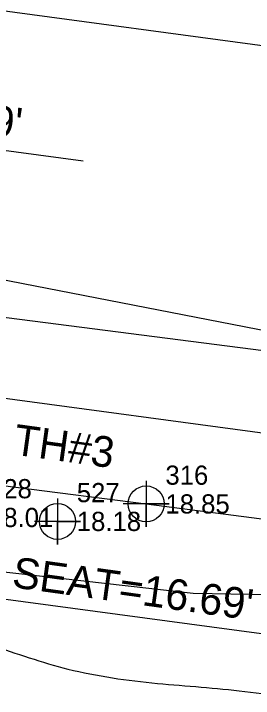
# Model space of a CAD drawing. Extents: x 2627243 to 2636458, y 566398 to 571062.
# Drawn here: x 2634722 to 2634753.1, y 569047.1 to 569136.3 of the extents above; entities that cross this region are included whole.
import ezdxf

# ---------------------------------------------------------------- set-up
doc = ezdxf.new("R2010")
doc.units = 0
for name, color, linetype in [('COGO Default Chain', 7, 'Continuous'), ('Exist Horizontal Alignment', 7, 'Continuous'), ('Exist Horizontal Baseline Alignment', 7, 'Continuous'), ('Exist Right of Way Line', 7, 'Continuous'), ('Exist Roads EOP', 7, 'Continuous'), ('Exist Roads EOP Cogo Elevation', 7, 'Continuous'), ('Exist Roads EOP Cogo Number', 7, 'Continuous'), ('Exist Roads EOP Cogo Point CELL', 7, 'Continuous'), ('Exist Structure Major Bridge Seat Top Elevation', 7, 'Continuous'), ('Exist Utilities Water Test Hole SUE Text', 7, 'Continuous'), ('Exist Utilities Water UG Line', 7, 'Continuous'), ('Exist Utilities Water UG Line Cogo Elevation', 7, 'Continuous'), ('Exist Utilities Water UG Line Cogo Number', 7, 'Continuous'), ('Exist Utilities Water UG Line Cogo Point CELL', 7, 'Continuous'), ('Exist Utilities Water UG Line SUE', 7, 'Continuous'), ('Exist Vegetation Woods Line', 7, 'Continuous')]:
    doc.layers.add(name, color=color, linetype=linetype)

# ---------------------------------------------------------------- blocks, each defined once
blk = doc.blocks.new('EXIST ROADS EOP COGO POINT')
at = {"layer": 'Exist Roads EOP Cogo Point CELL'}
blk.add_lwpolyline([(0, 0.06), (0, -0.06), (0, 0), (0.06, 0), (-0.06, 0)], dxfattribs=at)
blk.add_circle((0, 0), 0.0469, dxfattribs=at)
blk = doc.blocks.new('EXIST UTILITIES WATER UG LINE COGO POINT')
at = {"layer": 'Exist Utilities Water UG Line Cogo Point CELL'}
blk.add_lwpolyline([(0, 0.06), (0, -0.06), (0, 0), (0.06, 0), (-0.06, 0)], dxfattribs=at)
blk.add_circle((0, 0), 0.0469, dxfattribs=at)

msp = doc.modelspace()

# ---------------------------------------------------------------- linework, layer by layer
at = {"layer": 'COGO Default Chain'}
msp.add_line((2634072.78, 569173.542), (2634872.745, 569065.698), dxfattribs=at)
msp.add_line((2634072.78, 569173.542), (2634872.745, 569065.698), dxfattribs=at)
at = {"layer": 'Exist Horizontal Alignment'}
msp.add_line((2634072.78, 569173.542), (2634872.745, 569065.698), dxfattribs=at)
at = {"layer": 'Exist Horizontal Baseline Alignment'}
msp.add_line((2634680.61, 569109.426), (2635129.789, 569021.834), dxfattribs=at)
at = {"layer": 'Exist Right of Way Line'}
msp.add_line((2632427.744, 569445.763), (2634879.425, 569115.25), dxfattribs=at)
at = {"layer": 'Exist Roads EOP'}
msp.add_lwpolyline([(2634756.154, 569092.132), (2634708.467, 569098.258), (2634691.47, 569100.768), (2634667.356, 569105.661), (2634677.917, 569078.08), (2634688.445, 569077.775), (2634705.225, 569076.779), (2634739.193, 569072.427), (2634781.279, 569066.947)], dxfattribs=at)
at = {"layer": 'Exist Structure Major Bridge Seat Top Elevation'}
for points in [[(2634664.402, 569107.828), (2634688.681, 569122.796), (2634731.011, 569117.111)], [(2634677.043, 569076.496), (2634717.336, 569060.479), (2634757.082, 569055.141)]]:
    msp.add_lwpolyline(points, dxfattribs=at)
at = {"layer": 'Exist Utilities Water UG Line'}
msp.add_lwpolyline([(2634491.938, 569094.669), (2634504.797, 569090.483), (2634523.376, 569085.838), (2634745.287, 569060.808)], dxfattribs=at)
at = {"layer": 'Exist Utilities Water UG Line SUE'}
msp.add_lwpolyline([(2634745.287, 569060.808), (2634772.297, 569060.34), (2634799.288, 569058.161), (2634834.917, 569055.152), (2634876.42, 569050.415), (2634893.166, 569047.225), (2634922.728, 569041.343), (2634951.296, 569036.029), (2634995.745, 569027.256), (2635043.17, 569015.782), (2635070.418, 569008.301), (2635098.215, 568999.229), (2635119.896, 568992.516), (2635152.298, 568983.109), (2635187.641, 568971.231), (2635214.866, 568960.801)], dxfattribs=at)
at = {"layer": 'Exist Vegetation Woods Line'}
msp.add_spline([(2634648.605, 568711.487), (2634653.173, 568721.16), (2634653.751, 568723.17), (2634653.062, 568734.655), (2634652.681, 568736.88), (2634653.811, 568745.816), (2634654.682, 568748.012), (2634657.462, 568751.415), (2634662.006, 568762.101), (2634666.134, 568771.495), (2634670.477, 568781.848), (2634675.662, 568793.145), (2634680.221, 568804.456), (2634684.286, 568815.25), (2634687.607, 568827.217), (2634691.496, 568836.665), (2634694.841, 568847.62), (2634698.696, 568859.72), (2634702.614, 568870.42), (2634706.547, 568881.746), (2634708.602, 568893.118), (2634707.859, 568904.363), (2634707.859, 568914.434), (2634708.964, 568924.382), (2634711.312, 568935.939), (2634713.66, 568947.496), (2634714.717, 568959.47), (2634715.613, 568970.724), (2634714.708, 568981.25), (2634713.309, 568991.258), (2634709.845, 569001.605), (2634703.677, 569011.679), (2634697.548, 569021.366), (2634694.645, 569026.929), (2634691.128, 569037.035), (2634687.161, 569048.502), (2634684.142, 569055.224), (2634683.989, 569062.938), (2634686.083, 569063.851), (2634688.255, 569063.992), (2634698.877, 569060.848), (2634708.912, 569057.331), (2634719.002, 569054.055), (2634728.998, 569050.925), (2634740.663, 569049.057), (2634752.01, 569048.015), (2634763.876, 569046.479), (2634774.812, 569046.411), (2634786.684, 569047.139), (2634798.51, 569045.99), (2634811.388, 569044.478), (2634822.056, 569043.211), (2634833.271, 569042.703), (2634842.818, 569040.933), (2634849.22, 569038.612), (2634860.807, 569037.516), (2634873.074, 569036.645), (2634877.696, 569036.487), (2634881.962, 569037.542), (2634884.259, 569038.049)], degree=3, dxfattribs=at)

# ---------------------------------------------------------------- block references
at = {"layer": 'Exist Roads EOP Cogo Point CELL', "xscale": 50, "yscale": 50}
msp.add_blockref('EXIST ROADS EOP COGO POINT', (2634739.193, 569072.427), dxfattribs=at)
at = {"layer": 'Exist Utilities Water UG Line Cogo Point CELL', "xscale": 50, "yscale": 50}
msp.add_blockref('EXIST UTILITIES WATER UG LINE COGO POINT', (2634727.663, 569070.15), dxfattribs=at)

# ---------------------------------------------------------------- texts
at = {"layer": 'Exist Roads EOP Cogo Elevation'}
msp.add_text('18.85', height=2.5, dxfattribs=at).set_placement((2634741.693, 569071.177))
at = {"layer": 'Exist Roads EOP Cogo Number'}
msp.add_text('316', height=2.5, dxfattribs=at).set_placement((2634741.693, 569074.927))
at = {"layer": 'Exist Structure Major Bridge Seat Top Elevation'}
for rotation, p in [(353.69537, (2634691.537, 569123.438)), (352.12094, (2634721.613, 569061.596))]:
    msp.add_text("SEAT=16.69'", height=4, rotation=rotation, dxfattribs=at).set_placement(p)
at = {"layer": 'Exist Utilities Water Test Hole SUE Text'}
msp.add_text('TH#3', height=4, rotation=352.12092, dxfattribs=at).set_placement((2634721.788, 569078.872))
at = {"layer": 'Exist Utilities Water UG Line Cogo Elevation'}
for s, p in [('18.01', (2634718.737, 569069.413)), ('18.18', (2634730.163, 569068.9))]:
    msp.add_text(s, height=2.5, dxfattribs=at).set_placement(p)
at = {"layer": 'Exist Utilities Water UG Line Cogo Number'}
for s, p in [('528', (2634718.737, 569073.163)), ('527', (2634730.163, 569072.65))]:
    msp.add_text(s, height=2.5, dxfattribs=at).set_placement(p)

doc.saveas('drawing.dxf')
